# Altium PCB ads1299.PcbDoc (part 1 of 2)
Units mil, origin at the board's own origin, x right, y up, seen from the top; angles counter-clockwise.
Board outline 3937.01 x 3937.01 mil, 4 copper layers (Top Layer, internal_Layer 1, Internal_Layer 2, Bottom Layer), stack 23.756 mil thick; 175 components, 124 nets, 575 pads, 101 vias.
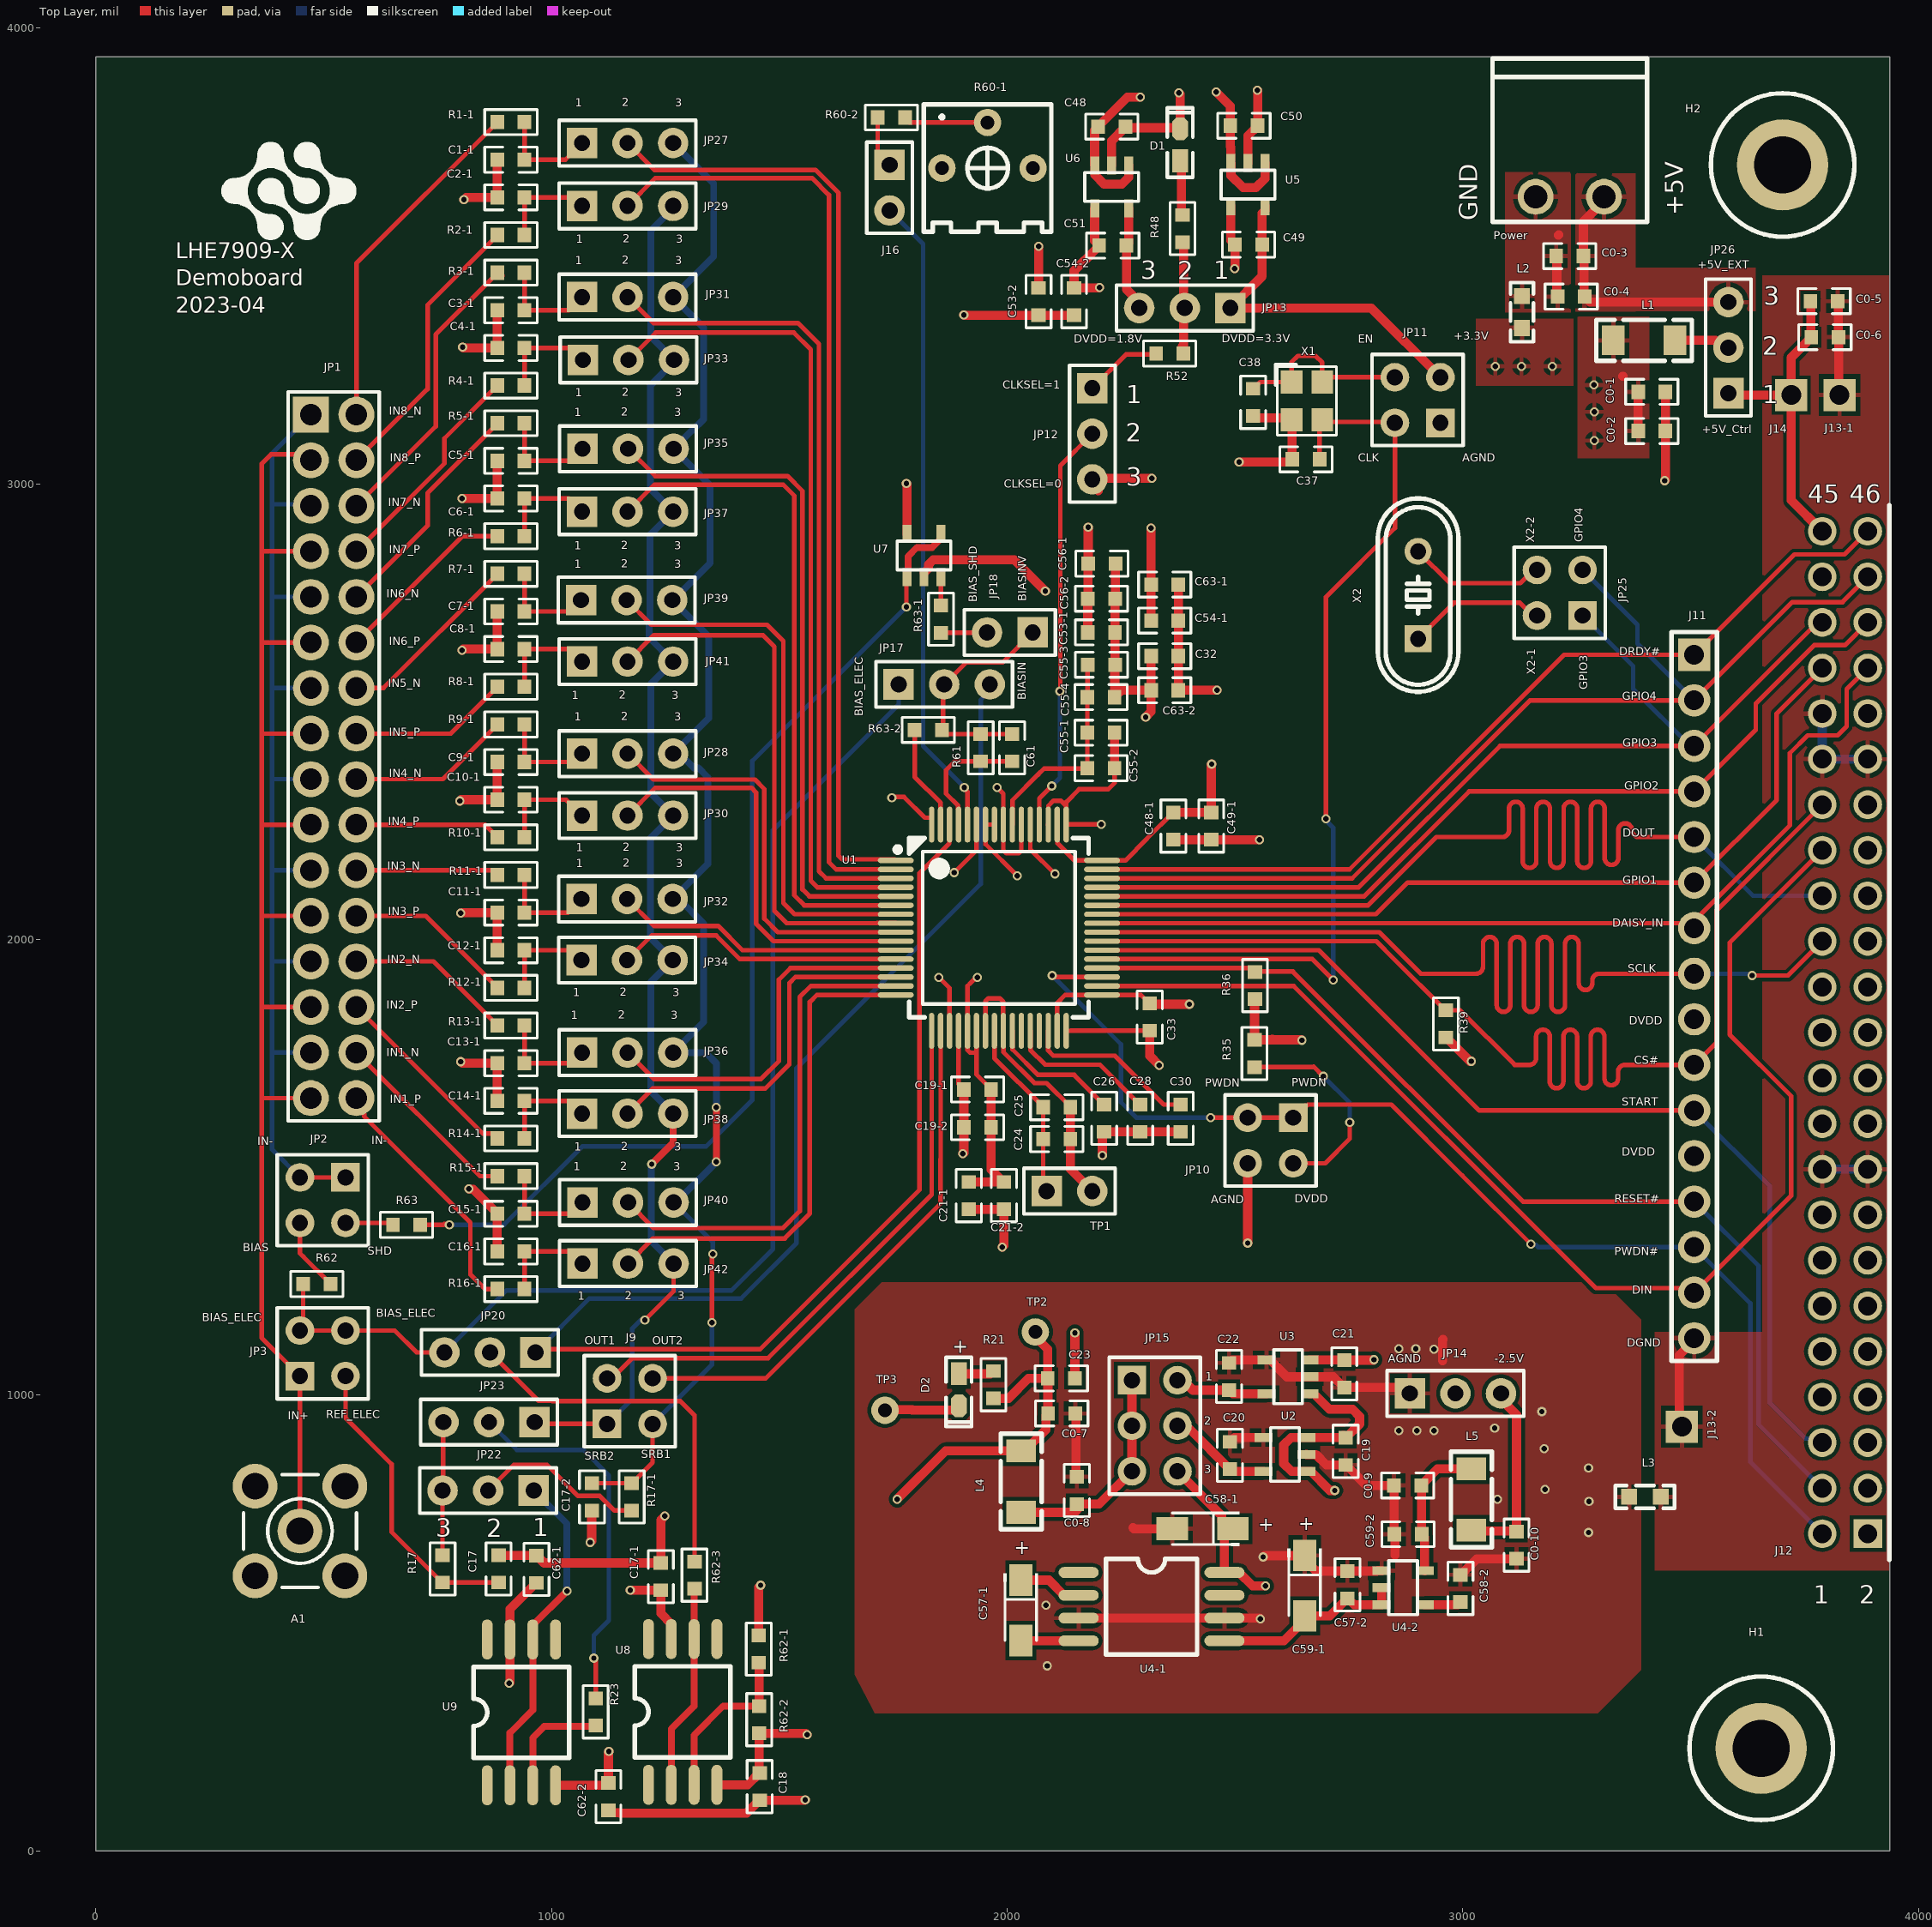
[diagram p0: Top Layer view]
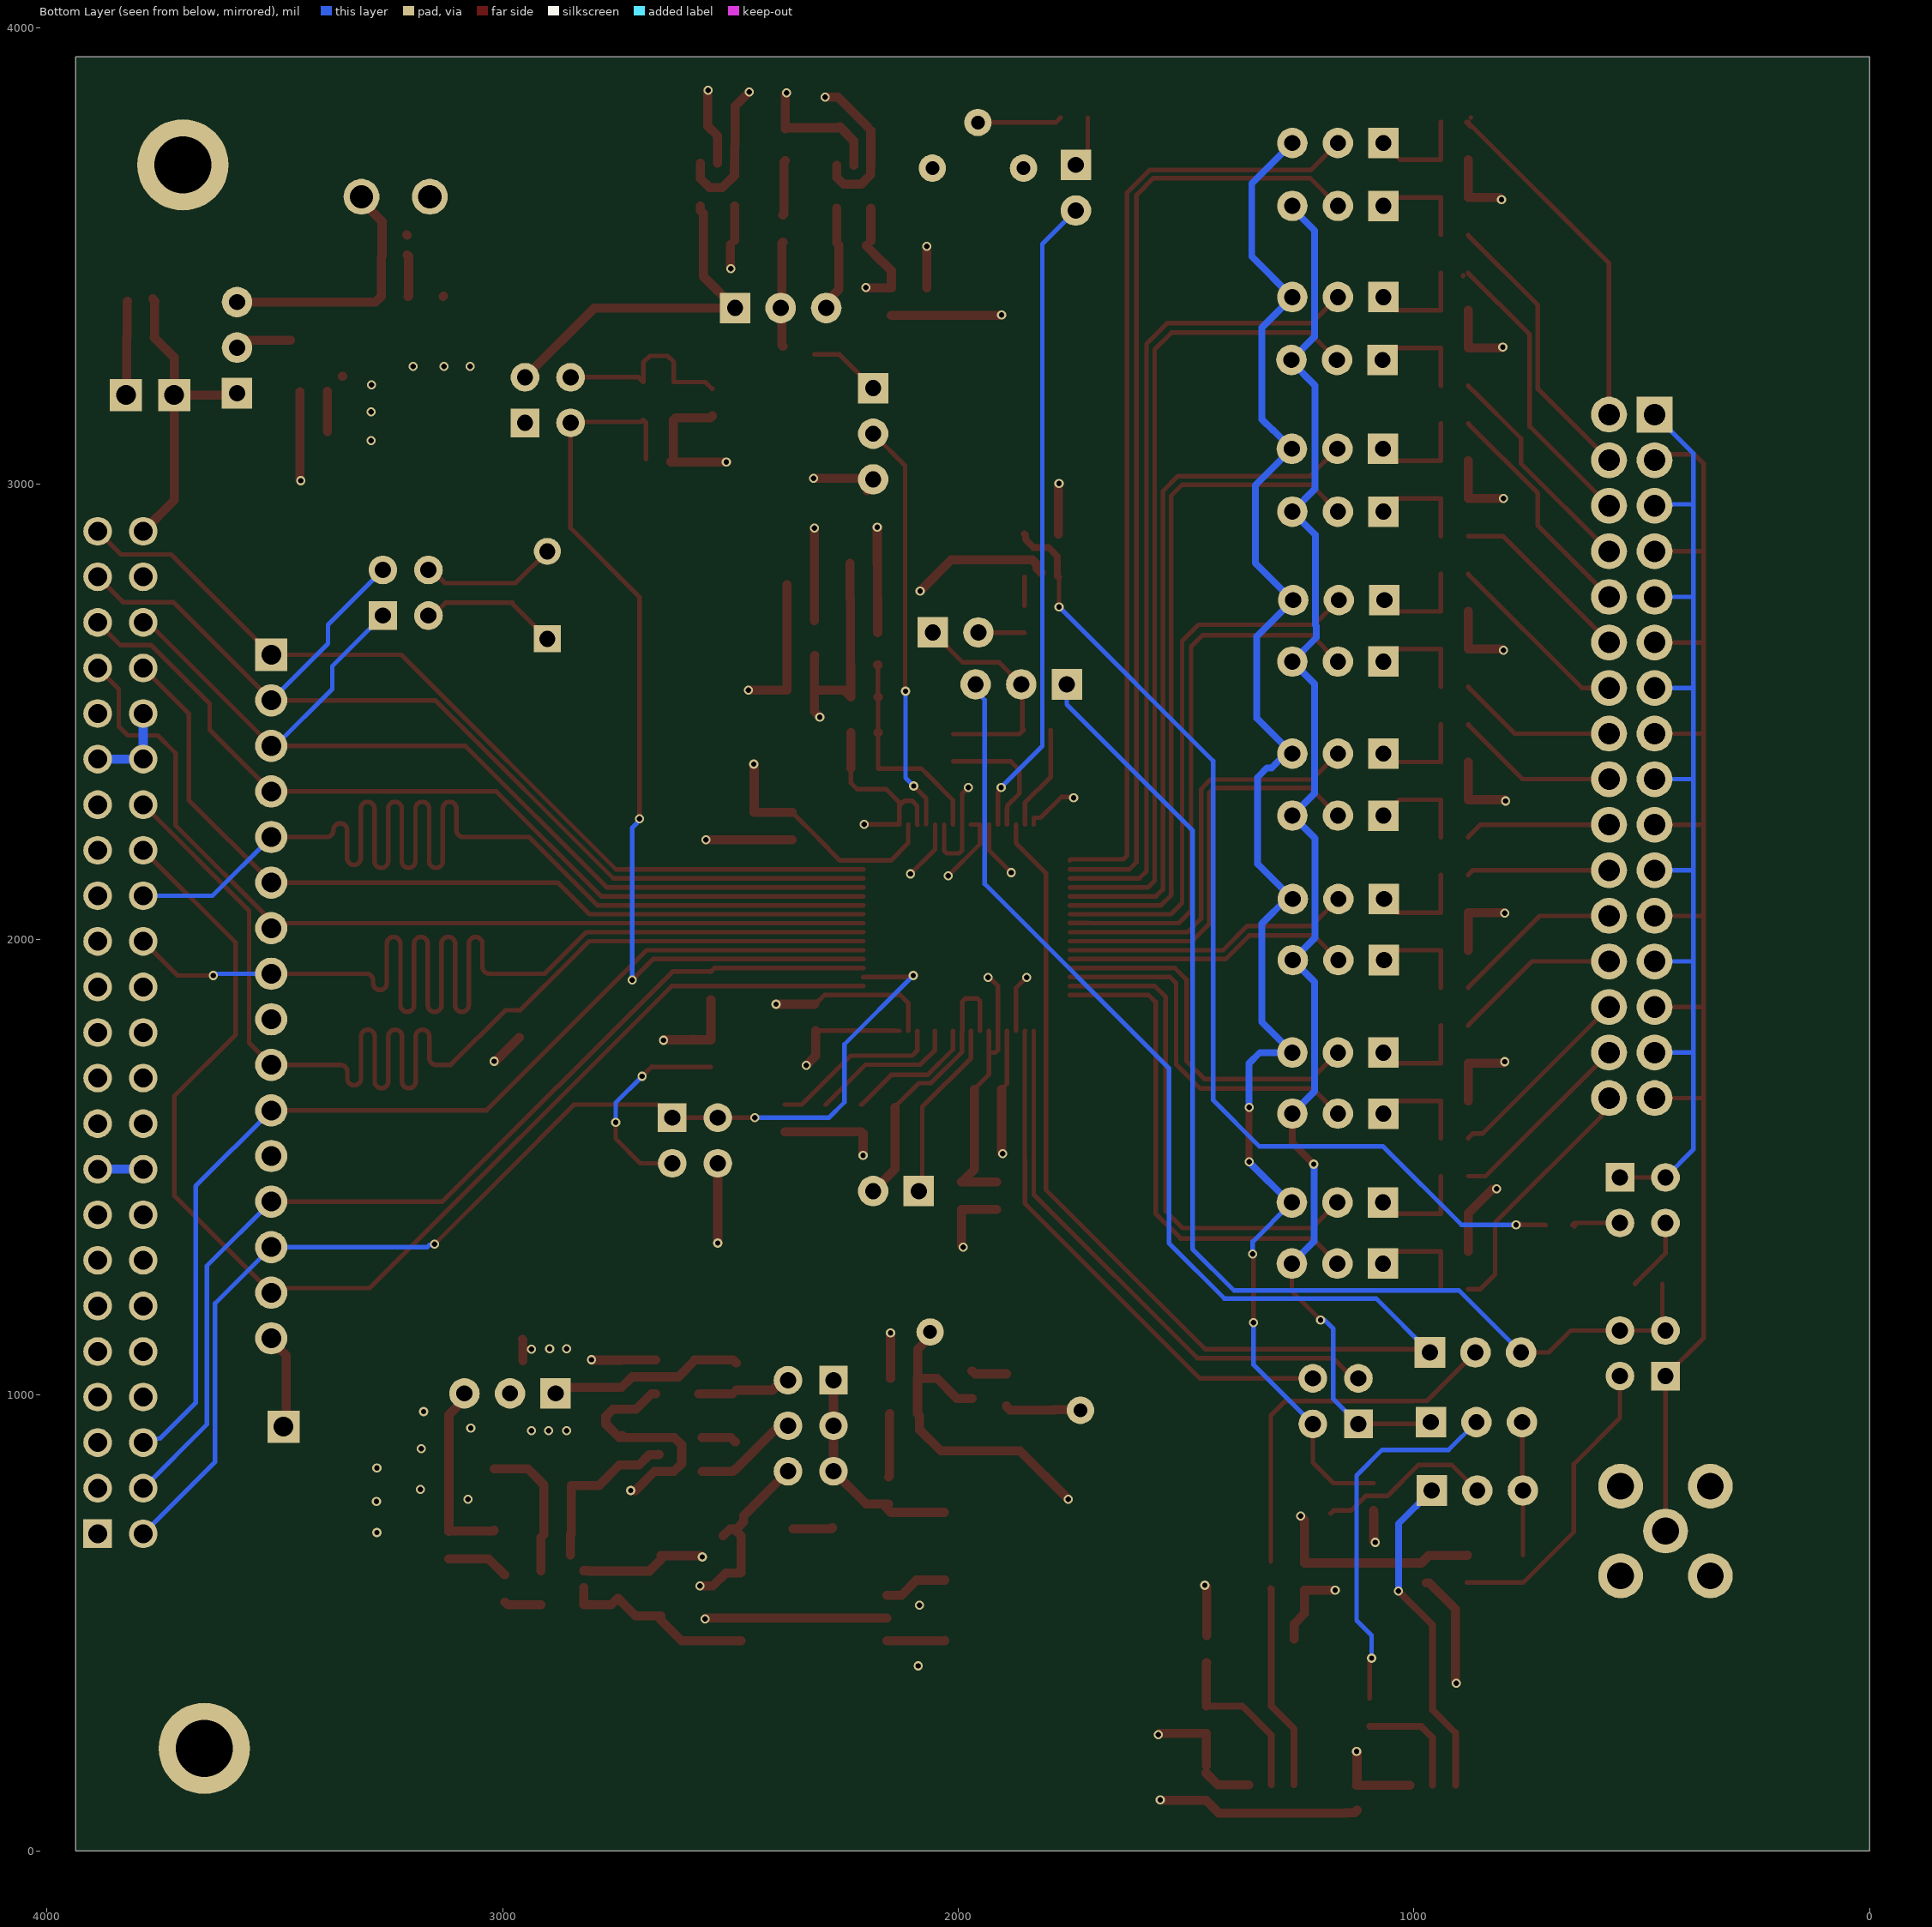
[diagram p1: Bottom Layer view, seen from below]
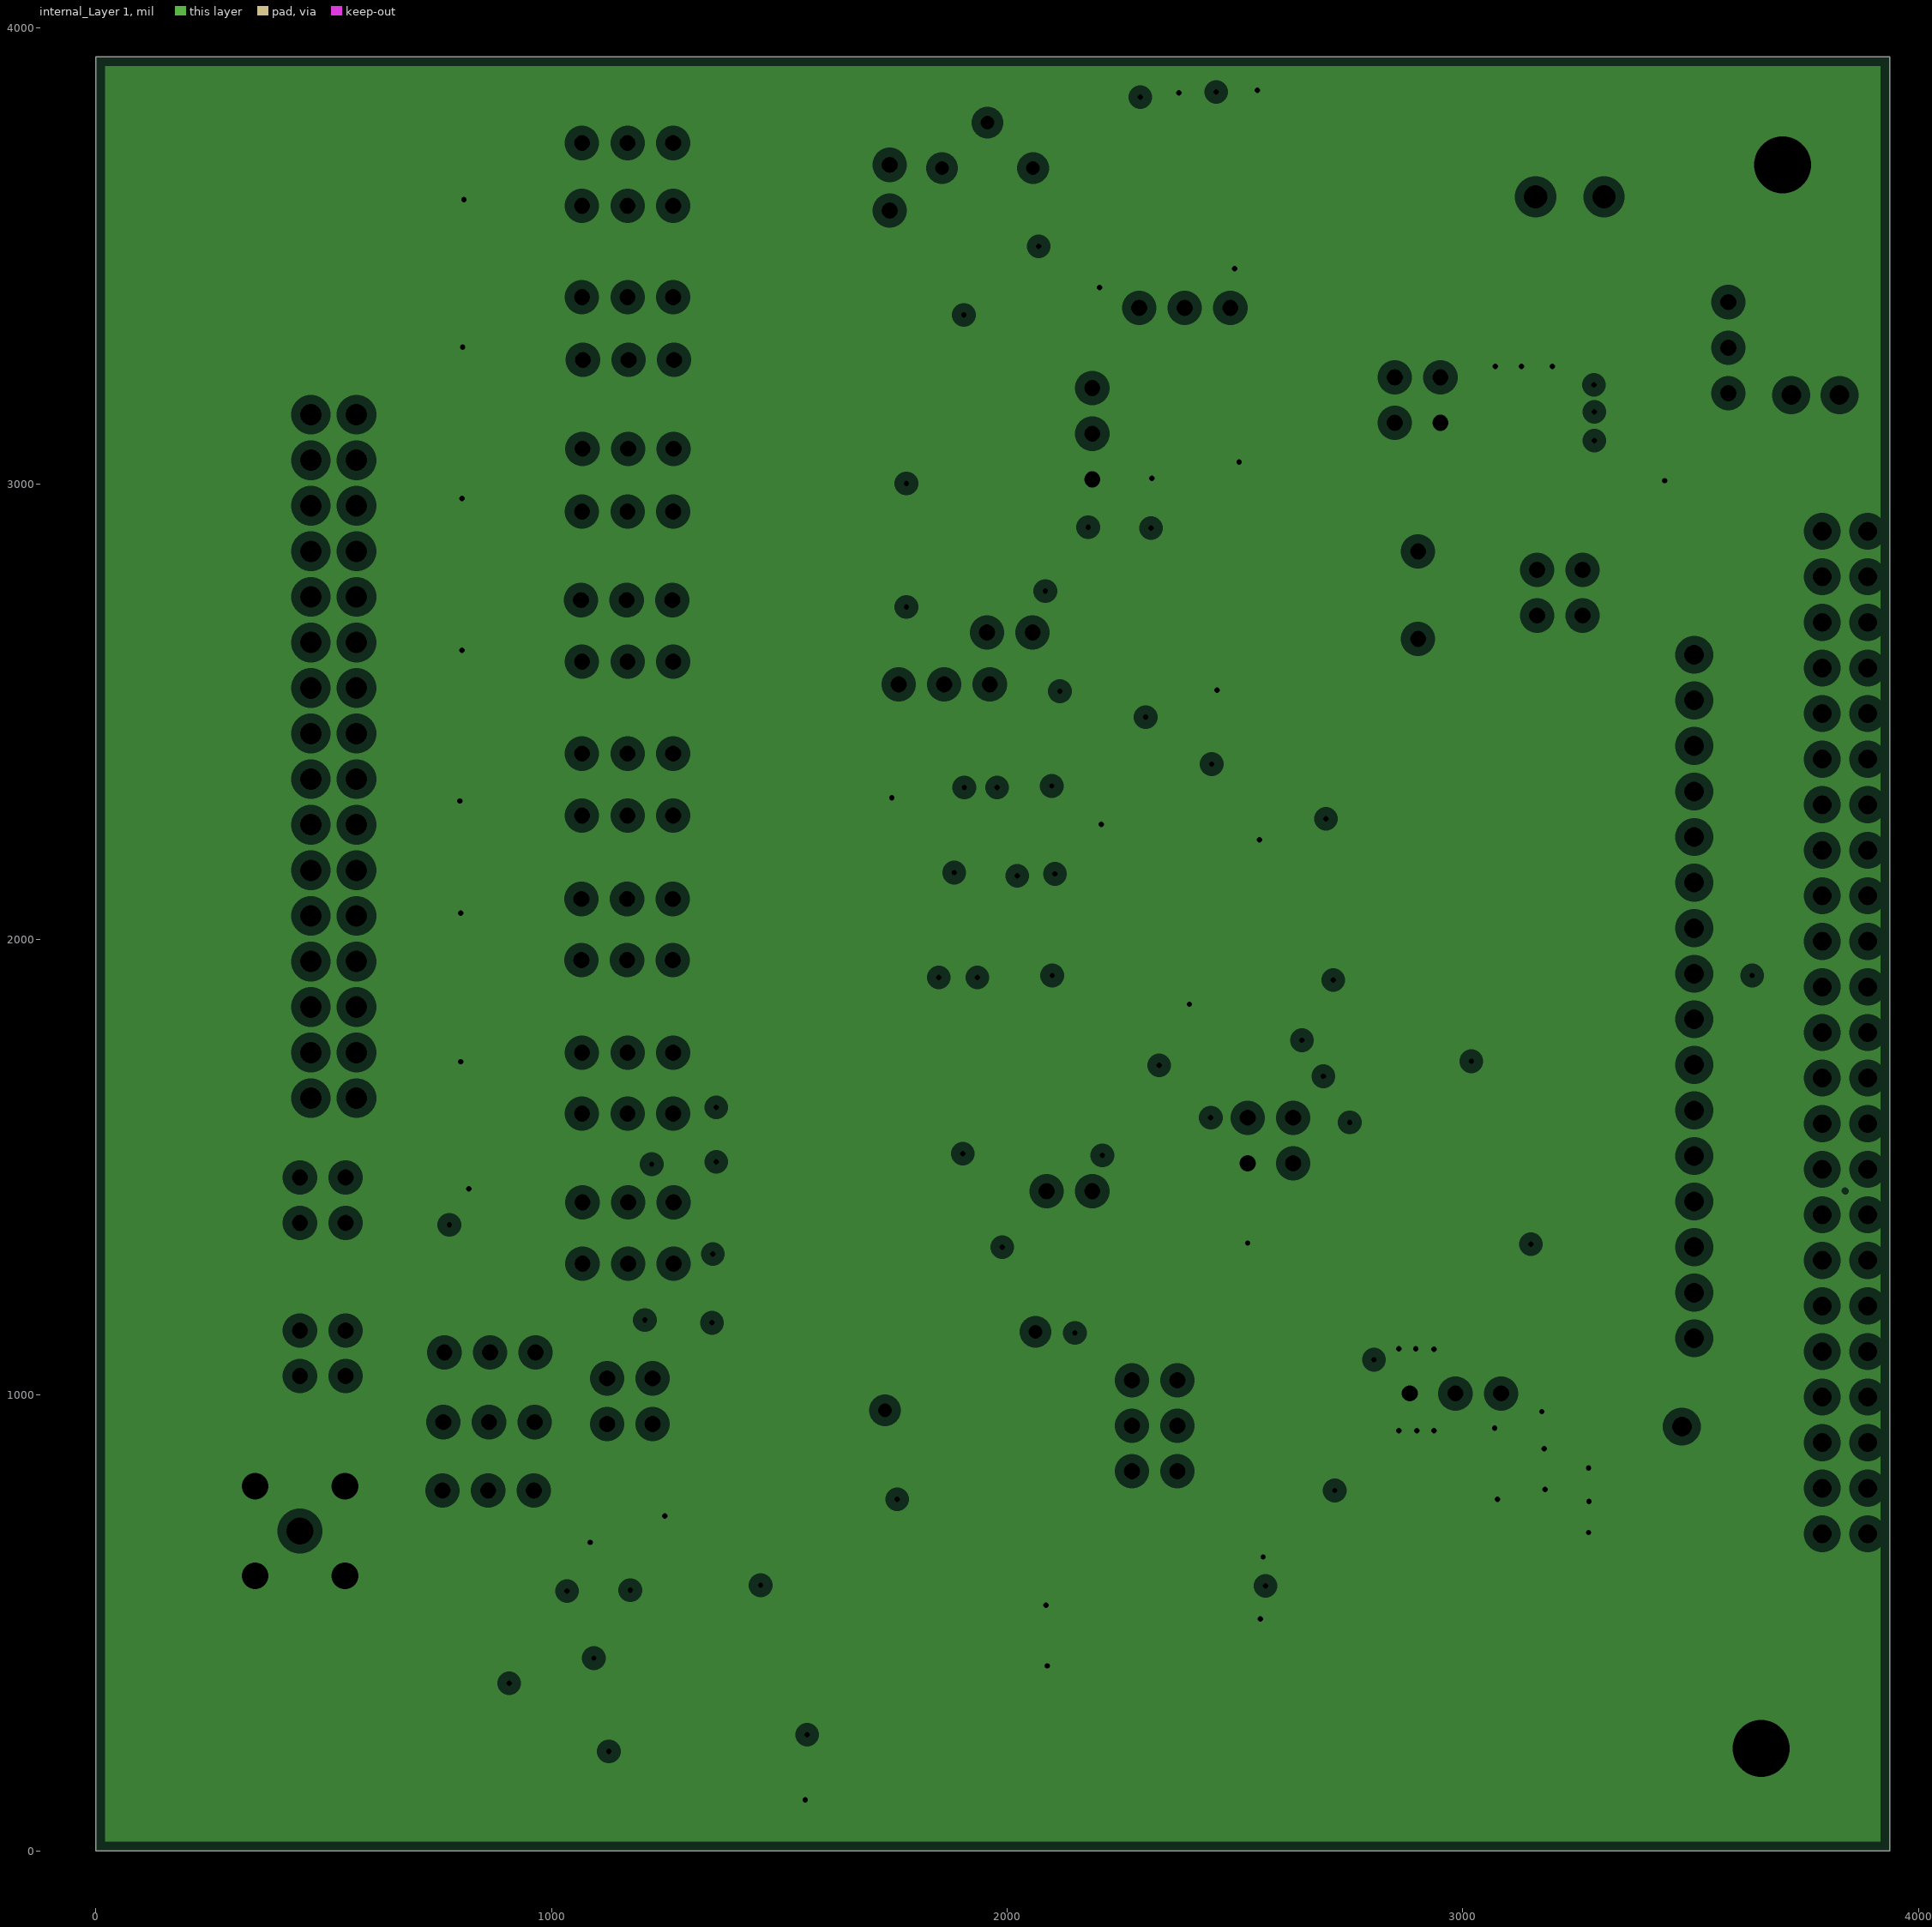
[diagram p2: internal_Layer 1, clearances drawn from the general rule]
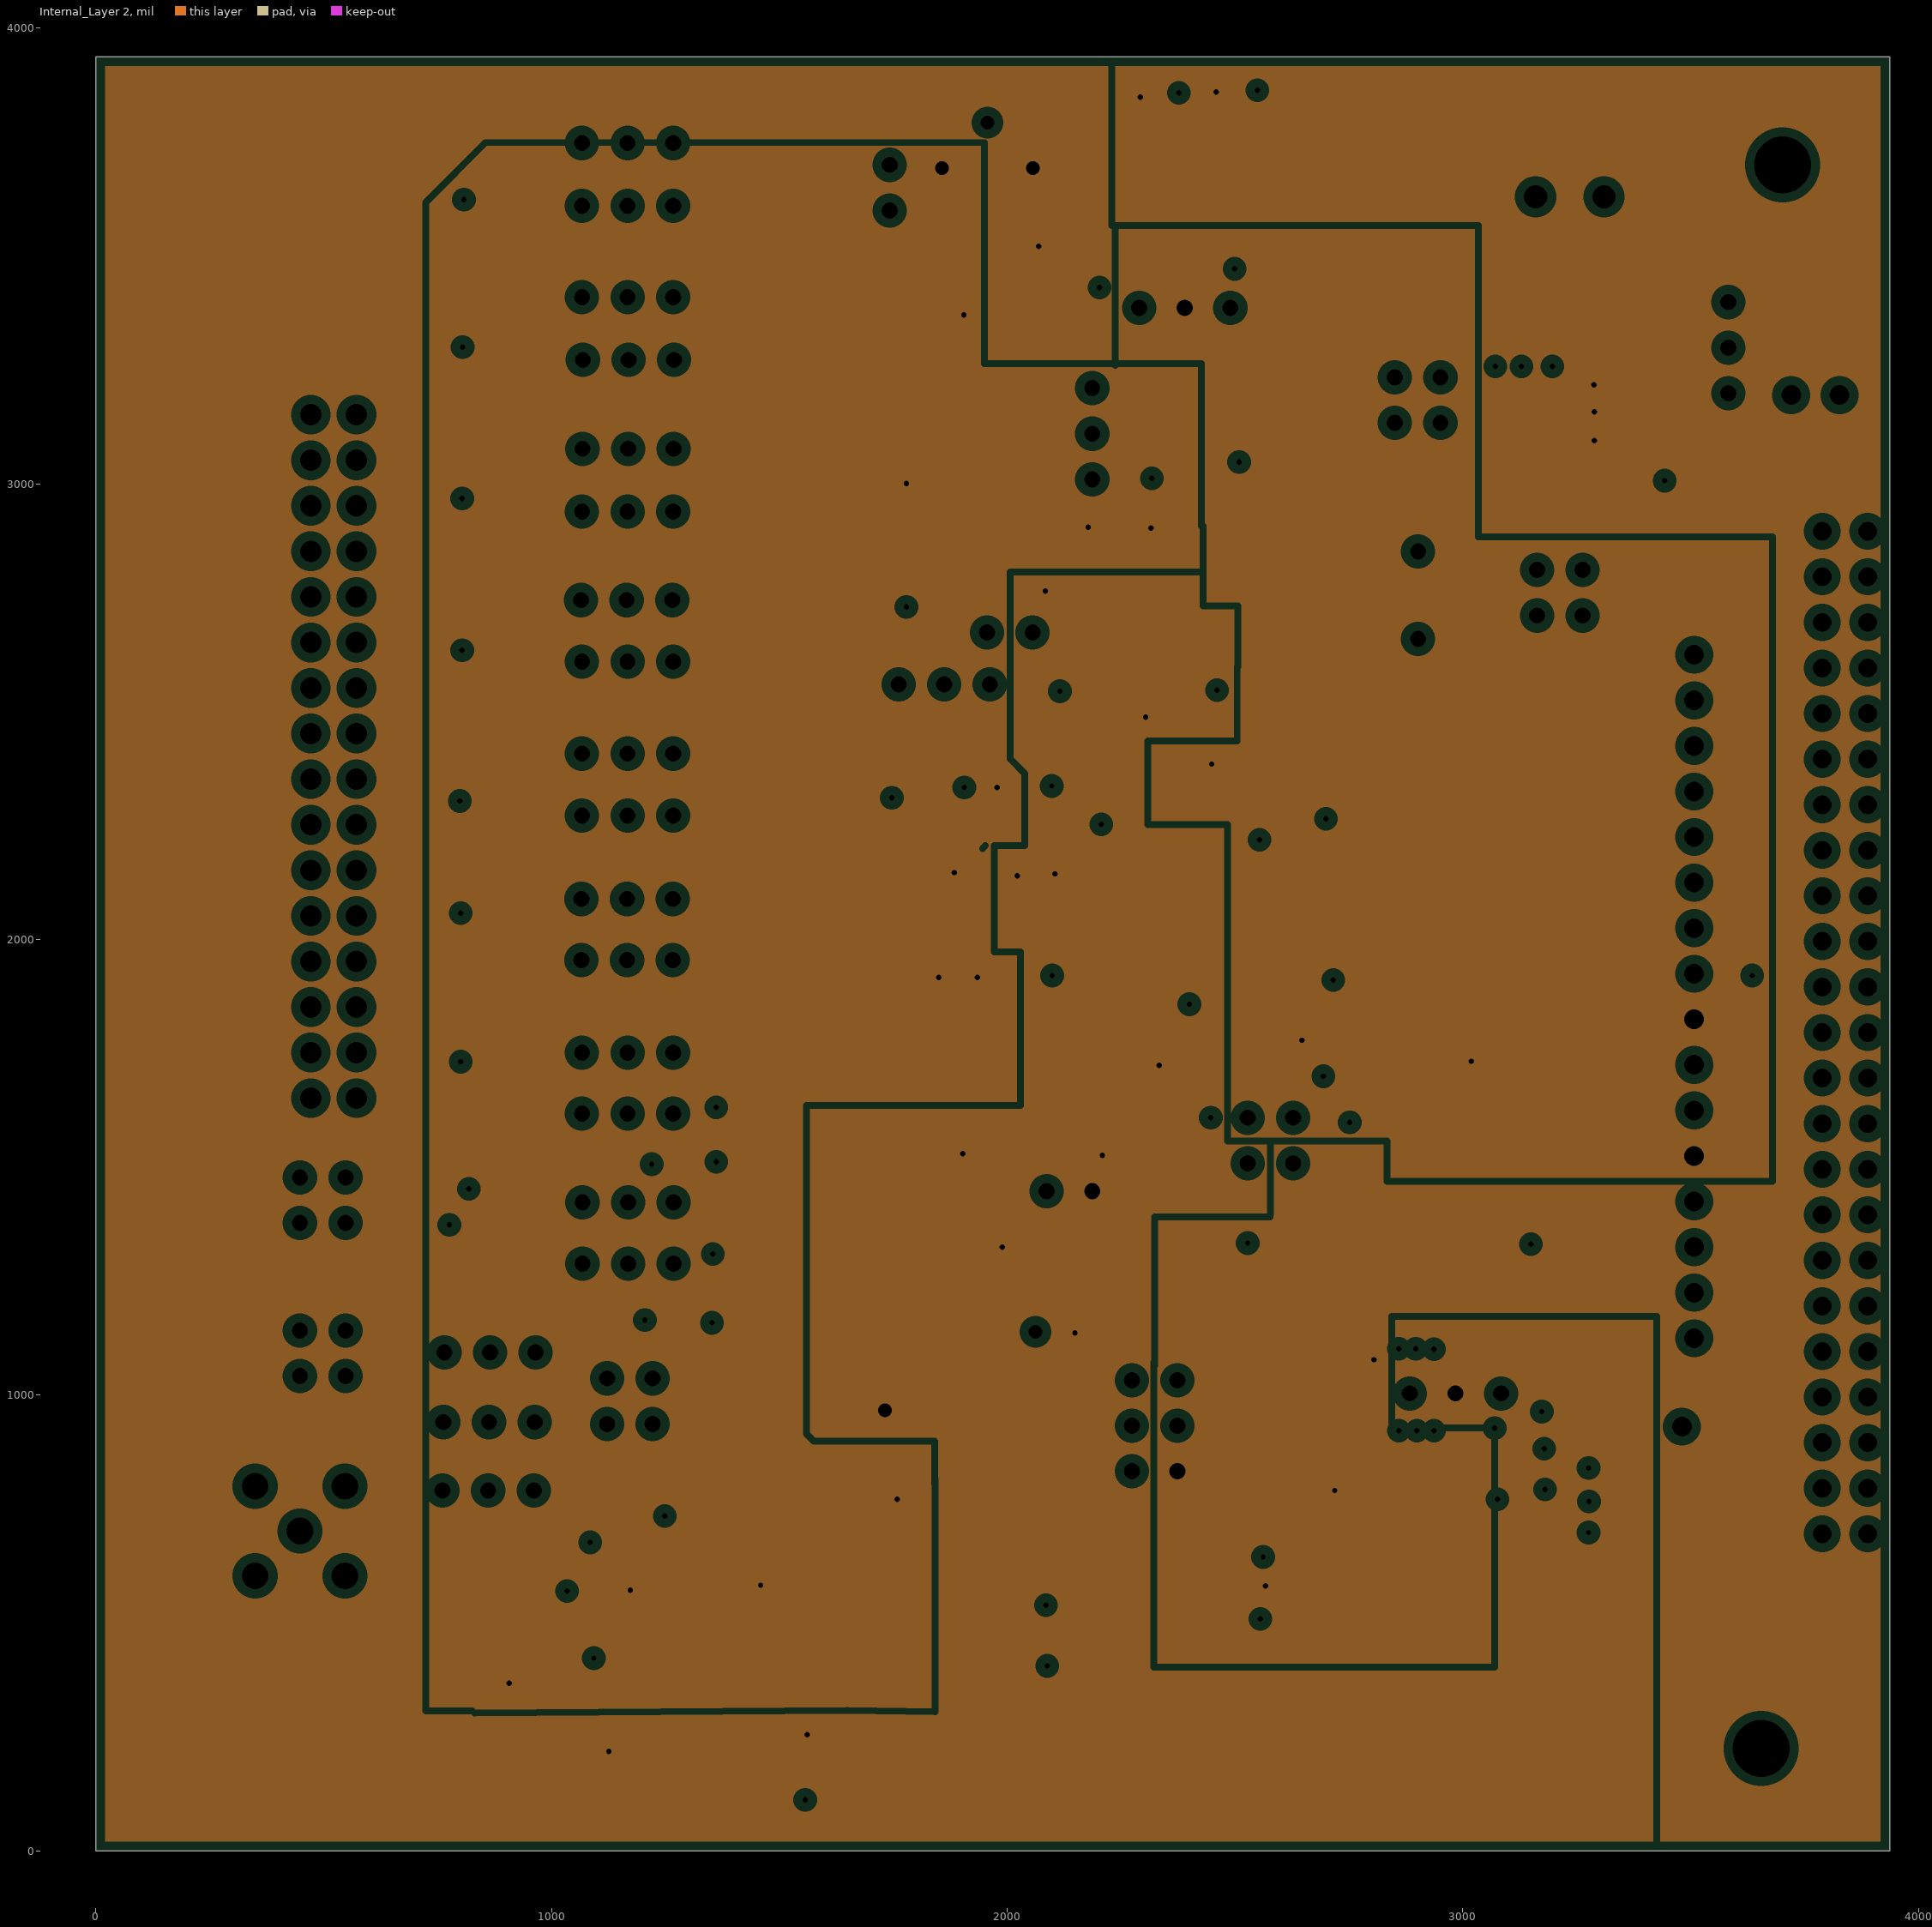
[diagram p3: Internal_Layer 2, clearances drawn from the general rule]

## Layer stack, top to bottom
Top Solder: solder mask 0.4, Solder Resist, Dk 3.5
Top Layer: signal copper 1.4
Dielectric 2: prepreg 2.8, PP-006, Dk 4.1
internal_Layer 1: plane copper 1.378, net AGND
Dielectric 1: dielectric 12.6, FR-4, Dk 4.8
Internal_Layer 2: plane copper 1.378, net (Multiple Nets)
Dielectric 3: prepreg 2.8, PP-006, Dk 4.1
Bottom Layer: signal copper 1.4
Bottom Solder: solder mask 0.4, Solder Resist, Dk 3.5

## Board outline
0,0 3937.01,0 3937.01,3937.01 0,3937.01

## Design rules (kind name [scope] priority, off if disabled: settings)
Clearance [All] p1: gap=8 ignorepadtopadclearanceinfootprint=TRUE except(0: Arc-Hole Track-Hole SMDPad-Hole THPad-Hole Via-Hole Fill-Hole Poly-Hole Region-Hole Text-Hole)
DiffPairsRouting [All] p1: maxlimit=10 minlimit=8 mostfreqgap=8 toplayer_minwidth=10 toplayer_maxwidth=15 toplayer_prefwidth=10 bottomlayer_minwidth=10 bottomlayer_maxwidth=15 bottomlayer_prefwidth=10 maxuncoupledlength=500
Height [All] p1: minheight=0 maxheight=5000 prefheight=500
HoleSize [All] p1: absolutevalues=TRUE maxlimit=200 minlimit=0 maxpercent=80.000 minpercent=20.000
HoleToHoleClearance [All] p1: gap=0 allowstackedmicrovias=TRUE
MatchedLengths [InNetClass('data')] p1: tolerance=10 checknetsindiffpair=FALSE checkdiffpairvsdiffpair=TRUE checkxsignals=TRUE checkothers=TRUE
MinimumSolderMaskSliver [All] p1: minsoldermaskwidth=0
PlaneClearance [All] p1: clearance=20
PlaneConnect [All] p1: planeconnectstyle=Relief reliefexpansion=20 reliefentries=4 reliefconductorwidth=10 reliefairgap=10
PolygonConnect [All] p1: thpad.connectstyle=Relief thpad.reliefconductorwidth=10 thpad.reliefentries=4 thpad.polygonreliefangle="90 Angle" thpad.airgapwidth=10 smdpad.connectstyle=Relief smdpad.reliefconductorwidth=10 smdpad.reliefentries=4 smdpad.polygonreliefangle="90 Angle" smdpad.airgapwidth=10 via.connectstyle=Direct via.reliefconductorwidth=10 via.reliefentries=4 via.polygonreliefangle="90 Angle" via.airgapwidth=10
RoutingVias [All] p1: holewidth=12 width=20 viastyle="Through Hole" minholewidth=12 minwidth=20 maxholewidth=12 maxwidth=20
SilkToSilkClearance [All] p1: silktosilkclearance=0
SilkToSolderMaskClearance [IsPad] p1: minsilkscreentomaskgap=0 clearancetoexposedcopper=TRUE
SolderMaskExpansion [All] p1: expansion=4
Width [InNetClass('All Nets')] p1: maxlimit=20 minlimit=10 preferedwidth=10 minimp=50.000000 maximp=50.000000 favimp=50.000000
21 further rules are at their usual default settings.

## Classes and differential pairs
component class ads1299_Regulators: C0-7 C0-8 C0-9 C0-10 C19 C20 C21 C22 C23 C48 C49 C50 C51 C57-1 C57-2 C58-1 C58-2 C59-1 C59-2 D1 D2 JP13 JP14 JP15 L4 L5 R21 R48 U2 U3 U4-1 U4-2 U5 U6
component class ads1299_main: C17-1 C17-2 C18 C19-1 C19-2 C21-1 C21-2 C24 C25 C26 C28 C30 C32 C33 C37 C38 C48-1 C49-1 C53-1 C53-2 C54-1 C54-2 C55-1 C55-2 C55-3 C55-4 C56-1 C56-2 C61 C62-1 C62-2 C63-1 C63-2 J9 J16 JP10 JP11 JP12 JP17 JP18 JP20 JP22 JP23 R17-1 R23 R35 R36 R39 R52 R60-1 R60-2 R61 R62-1 R62-2 R62-3 R63-1 R63-2 TP1 TP2 TP3 U1 U7 U8 U9 X1
component class ads1299_Interface: C0-1 C0-2 C0-3 C0-4 C0-5 C0-6 J11 J12 J13-1 J13-2 J14 JP25 JP26 L1 L2 L3 Power X2
component class ads1299_Ain: A1 C1-1 C2-1 C3-1 C4-1 C5-1 C6-1 C7-1 C8-1 C9-1 C10-1 C11-1 C12-1 C13-1 C14-1 C15-1 C16-1 C17 H1 H2 JP1 JP2 JP3 JP27 JP28 JP29 JP30 JP31 JP32 JP33 JP34 JP35 JP36 JP37 JP38 JP39 JP40 JP41 JP42 R1-1 R2-1 R3-1 R4-1 R5-1 R6-1 R7-1 R8-1 R9-1 R10-1 R11-1 R12-1 R13-1 R14-1 R15-1 R16-1 R17 R62 R63
differential pair IN8: +IN8_P -IN8_N
differential pair IN7: +IN7_P -IN7_N
differential pair IN6: +IN6_P -IN6_N
differential pair IN5: +IN5_P -IN5_N
differential pair IN4: +IN4_P -IN4_N
differential pair IN3: +IN3_P -IN3_N
differential pair IN2: +IN2_P -IN2_N
differential pair IN1: +IN1_P -IN1_N

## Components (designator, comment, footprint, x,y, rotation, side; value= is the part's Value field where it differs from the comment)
A1 "SMA/SMB" SMB_V-RJ45 448,702 r0 top
C0-1 "10uF" 0603C 3414.92,3202 r180 top
C0-2 "0.1uF" 0603C 3415,3116 r180 top
C0-3 "10uF" 0603C 3235,3500 r0 top
C0-4 "0.1uF" 0603C 3238,3411 r0 top
C0-5 "10uF" 0603C 3793.08,3401 r180 top
C0-6 "0.1uF" 0603C 3795,3322 r180 top
C0-7 "10uF" 0603C 2120,960 r180 top
C0-8 "10uF" 0603C 2153,790.92 r270 top
C0-9 "10uF" 0603C 2879.08,802 r0 top
C0-10 "10uF" 0603C 3118,671 r90 top
C1-1 "4.7nF" 0603C 911,3711.39 r0 top
C2-1 "4.7nF" 0603C 911,3628.77 r180 top
C3-1 "4.7nF" 0603C 911,3380.94 r0 top
C4-1 "4.7nF" 0603C 911,3298.32 r180 top
C5-1 "4.7nF" 0603C 911,3050.48 r0 top
C6-1 "4.7nF" 0603C 911,2967.87 r180 top
C7-1 "4.7nF" 0603C 911,2720.03 r0 top
C8-1 "4.7nF" 0603C 911,2637.42 r180 top
C9-1 "4.7nF" 0603C 911,2389.58 r0 top
C10-1 "4.7nF" 0603C 911,2306.97 r180 top
C11-1 "4.7nF" 0603C 911,2059.13 r0 top
C12-1 "4.7nF" 0603C 911,1976.52 r180 top
C13-1 "4.7nF" 0603C 911,1728.68 r0 top
C14-1 "4.7nF" 0603C 911,1646.06 r180 top
C15-1 "4.7nF" 0603C 911,1398.23 r0 top
C16-1 "4.7nF" 0603C 911,1315.61 r180 top
C17 "4.7nF" 0603C 884,619 r270 top
C17-1 "1uF" 0603C 1240,602 r270 top
C17-2 "NI" 0603C 1089,777 r90 top
C18 "1uF" 0603C 1457,141 r270 top
C19 "1uF" 0603C 2743,876.92 r90 top
C19-1 "1uF" 0603C 1935,1671 r0 top
C19-2 "0.1uF" 0603C 1935,1588 r0 top
C20 "1uF" 0603C 2489,867.92 r270 top
C21 "1uF" 0603C 2740,1047 r90 top
C21-1 "0.1uF" 0603C 1916,1438 r90 top
C21-2 "1uF" 0603C 1993,1438 r90 top
C22 "1uF" 0603C 2487,1041 r270 top
C23 "0.1uF" 0603C 2119,1037 r180 top
C24 "10uF" 0603C 2109,1562 r0 top
C25 "0.1uF" 0603C 2109,1632 r180 top
C26 "1uF" 0603C 2213,1608 r90 top
C28 "22uF/100uF" 0603C 2292,1608 r90 top
C30 "1uF" 0603C 2381,1608 r90 top
C32 "1uF" 0603C 2346,2622 r180 top
C33 "1uF" 0603C 2313,1830.08 r270 top
C37 "15pF" 0603C 2656,3054 r0 top
C38 "0.01uF" 0603C 2540,3178.92 r270 top
C48 "1uF" 0603C 2229.92,3784 r180 top
C48-1 "0.1uF" 0603C 2365,2249 r90 top
C49 "1uF" 0603C 2530,3525 r0 top
C49-1 "1uF" 0603C 2448,2249 r90 top
C50 "1uF" 0603C 2519.92,3786 r180 top
C51 "1uF" 0603C 2232,3523 r0 top
C53-1 "0.1uF" 0603C 2206.92,2674 r180 top
C53-2 "1uF" 0603C 2069,3400 r270 top
C54-1 "0.1uF" 0603C 2346,2700 r180 top
C54-2 "1uF" 0603C 2147,3400 r270 top
C55-1 "0.1uF" 0603C 2206,2454 r180 top
C55-2 "1uF" 0603C 2206,2376 r180 top
C55-3 "NI" 0603C 2207,2603 r0 top
C55-4 "NI" 0603C 2206,2532 r0 top
C56-1 "0.1uF" 0603C 2208,2825 r180 top
C56-2 "1uF" 0603C 2207,2748 r180 top
C57-1 "10uF" Tantalum_cap 2030,528 r270 top value=1uF
C57-2 "1uF" 0603C 2747,584 r270 top
C58-1 "0.1uF" Tantalum_cap 2429,707 r180 top value=1uF
C58-2 "1uF" 0603C 2995,576 r270 top
C59-1 "10uF" Tantalum_cap 2653,582 r270 top value=1uF
C59-2 "1uF" 0603C 2880,695 r0 top
C61 "0.01uF" 0603C 2011,2421 r270 top
C62-1 "1uF" 0603C 967,618 r270 top
C62-2 "1uF" 0603C 1125,119 r270 top
C63-1 "0.1uF" 0603C 2346,2779 r180 top
C63-2 "0.1uF" 0603C 2346,2547 r0 top
D1 "绿灯 0603" "LED 0603G" 2380,3744 r90 top
D2 "绿灯 0603" "LED 0603G" 1894,1012 r270 top
H1 "M3" M3x4_L 3655,225 r0 top
H2 "M3" M3x4_L 3702,3700 r0 top
J9 "Header 2X2" HDR2.54-LI-2x2P 1172,987 r0 top
J11 "KH-2.54PH180-1X16P-L11.5" HDR-TH_16P-P2.54 3508,1875 r270 top
J12 "X6521WR-2x23H-C30D60" HDR-TH_2x23P-P2.54-Bent 3839,1796 r90 top
J13-1 "Header_1P" HDR-TH_1P 3827,3195 r0 top
J13-2 "Header_1P" HDR-TH_1P 3481,931 r0 top
J14 "Header_1P" HDR-TH_1P 3721,3195 r0 top
J16 "Header_2P_2.54" HDR2.54-LI-2P 1742,3650 r270 top
JP1 "B-2100S32P-B110" HDR-TH_32P-P2.54-V-M-R2-C16-S2.54 522,2402 r270 top
JP2 "Header 2X2" HDR2.54-LI-2x2P 498,1428 r180 top
JP3 "Header 2X2" HDR2.54-LI-2x2P 498,1092 r0 top
JP10 "Header 2X2" HDR2.54-LI-2x2P 2578,1559 r180 top
JP11 "Header 2X2_2.54" HDR2.54-LI-2x2P 2901,3184 r90 top
JP12 "HDR-1X3" HDR2.54-LI-3P 2187,3110 r270 top
JP13 "HDR-1X3" HDR2.54-LI-3P 2390,3386 r180 top
JP14 "HDR-1X3" HDR2.54-LI-3P 2984,1004 r0 top
JP15 "Header 3X2" HDR2.54-LI-2x3P 2324,933 r270 top
JP17 "HDR-1X3" HDR2.54-LI-3P 1862,2560 r0 top
JP18 "Header_2P_2.54" HDR2.54-LI-2P 2006,2674 r180 top
JP20 "HDR-1X3" HDR2.54-LI-3P 865,1094 r180 top
JP22 "HDR-1X3" HDR2.54-LI-3P 861,791 r180 top
JP23 "HDR-1X3" HDR2.54-LI-3P 863,941 r180 top
JP25 "Header 2X2" HDR2.54-LI-2x2P 3213,2761 r90 top
JP26 "HDR-1X3" HDR2.54-LI-3P 3583,3299 r90 top
JP27 "HDR-1X3" HDR2.54-LI-3P 1167,3748 r0 top
JP28 "HDR-1X3" HDR2.54-LI-3P 1167,2408 r0 top
JP29 "HDR-1X3" HDR2.54-LI-3P 1167,3610 r0 top
JP30 "HDR-1X3" HDR2.54-LI-3P 1167,2272 r0 top
JP31 "HDR-1X3" HDR2.54-LI-3P 1167,3410 r0 top
JP32 "HDR-1X3" HDR2.54-LI-3P 1166,2089 r0 top
JP33 "HDR-1X3" HDR2.54-LI-3P 1169,3272 r0 top
JP34 "HDR-1X3" HDR2.54-LI-3P 1166,1955 r0 top
JP35 "HDR-1X3" HDR2.54-LI-3P 1168,3077 r0 top
JP36 "HDR-1X3" HDR2.54-LI-3P 1167,1752 r0 top
JP37 "HDR-1X3" HDR2.54-LI-3P 1167,2939 r0 top
JP38 "HDR-1X3" HDR2.54-LI-3P 1167,1618 r0 top
JP39 "HDR-1X3" HDR2.54-LI-3P 1165,2745 r0 top
JP40 "HDR-1X3" HDR2.54-LI-3P 1168,1423 r0 top
JP41 "HDR-1X3" HDR2.54-LI-3P 1167,2610 r0 top
JP42 "HDR-1X3" HDR2.54-LI-3P 1168,1289 r0 top
L1 "3.3uH" "L 1206" 3398,3315 r180 top
L2 "0Ω@100MHz" "L 0603" 3130,3377 r270 top
L3 "0Ω@100MHz" "L 0603" 3400,777 r0 top
L4 "3.3uH" "L 1206" 2031,810.5 r270 top
L5 "3.3uH" "L 1206" 3019,771 r270 top
Power "CONN-TH-F3.81-2P" CONN-TH_XY2500R-F-3.81-2P 3235,3630 r180 top
R1-1 "4.99kΩ" 0603R 911,3794 r0 top
R2-1 "4.99kΩ" 0603R 911,3546.16 r0 top
R3-1 "4.99kΩ" 0603R 911,3463.55 r0 top
R4-1 "4.99kΩ" 0603R 911,3215.71 r0 top
R5-1 "4.99kΩ" 0603R 911,3133.1 r0 top
R6-1 "4.99kΩ" 0603R 911,2885.26 r0 top
R7-1 "4.99kΩ" 0603R 911,2802.65 r0 top
R8-1 "4.99kΩ" 0603R 911,2554.81 r0 top
R9-1 "4.99kΩ" 0603R 911,2472.19 r0 top
R10-1 "4.99kΩ" 0603R 911,2224.35 r0 top
R11-1 "4.99kΩ" 0603R 911,2141.74 r0 top
R12-1 "4.99kΩ" 0603R 911,1893.9 r0 top
R13-1 "4.99kΩ" 0603R 911,1811.29 r0 top
R14-1 "4.99kΩ" 0603R 911,1563.45 r0 top
R15-1 "4.99kΩ" 0603R 911,1480.84 r0 top
R16-1 "4.99kΩ" 0603R 911,1233 r0 top
R17 "4.99kΩ" 0603R 761,619 r270 top
R17-1 "0Ω" 0603R 1176,777 r90 top
R21 "100Ω" 0603R 1970,1023 r270 top
R23 "0Ω" 0603R 1097,305 r270 top
R35 "10KΩ" 0603R 2543,1750 r270 top
R36 "10KΩ" 0603R 2544,1899 r270 top
R39 "10KΩ" 0603R 2963,1815 r90 top
R48 "100Ω" 0603R 2385,3560.08 r270 top
R52 "10KΩ" 0603R 2357,3286 r0 top
R60-1 "可变电阻10kΩ" RES-ADJ-TH_3362P 1957,3743 r0 top value=10kΩ
R60-2 "0Ω" 0603R 1746,3804 r180 top
R61 "392KΩ" 0603R 1942,2421 r90 top
R62 "4.99kΩ" 0603R 485,1244 r180 top
R62-1 "2MΩ" 0603R 1455,443 r90 top
R62-2 "2MΩ" 0603R 1456,288 r90 top
R62-3 "0Ω" 0603R 1314,605.08 r90 top
R63 "4.99kΩ" 0603R 682,1374 r0 top
R63-1 "0Ω/5kΩ" 0603R 1855,2703 r270 top
R63-2 "0Ω" 0603R 1827,2460 r0 top
TP1 "Header_2P_2.54" HDR2.54-LI-2P 2137,1448 r0 top
TP2 "测试点" TestPoint_Pad 2062,1139 r90 top
TP3 "测试点" TestPoint_Pad 1732,967 r180 top
U1 "ADS129x" LQFP-64 1982,2026 r270 top
U2 "LP5907MFX-3.0/NOPB" SOT23-5 2657,832.6 r90 top
U3 "LP5907MFX-2.5/NOPB" SOT23-5 2664,1003 r90 top
U4-1 "ICL7660M/TR" SOIC-8 2157,611 r0 top
U4-2 "TPS72325DBVR" SOT23-5 2822,615 r270 top
U5 "LP5907MFX-3.3/NOPB" SOT23-5 2566,3704 r180 top
U6 "LP5907MFX-1.8/NOPB" SOT23-5 2267,3699 r180 top
U7 "TLV9061IDBVR" SOT23-5 1780.2,2795.51 r0 top
U8 "OPA376AID" SOIC-8 1213,145 r90 top
U9 "OPA376AID" SOIC-8 859,144 r90 top
X1 "SX3M2.048M20F30TNN" "OSC 3225-4P" 2658,3182 r270 top value=2.048MHz
X2 "X49SD4096MSD2SC" HC-49US 2902,2756 r90 top value=4.096MHz

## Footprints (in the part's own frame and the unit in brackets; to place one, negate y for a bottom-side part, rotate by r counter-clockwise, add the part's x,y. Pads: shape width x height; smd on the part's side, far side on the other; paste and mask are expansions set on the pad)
0603C [mm]
  rect 0.76x0.8 smd: 1(-0.76,0) 2(0.76,0)
  silkscreen extent -1.46,-0.7 1.46,0.7, body extent -0.8,-0.4 0.8,0.4, height 0.3
0603R [mm]
  rect 0.76x0.8 smd: 1(-0.76,0) 2(0.76,0)
  silkscreen extent -1.46,-0.7 1.46,0.7, body extent -0.8,-0.41 0.8,0.41, height 0.45
CONN-TH_XY2500R-F-3.81-2P [mm]
  round 2 hole 1.3 mask+0.051: 1(-1.905,0) 2(1.905,0)
  silkscreen extent -4.31,-7.7 4.31,1.4
HC-49US [mm]
  rect 1.5x1.5 hole 0.9 mask+0.051: 1(-2.44,0)
  round 1.5 hole 0.9 mask+0.051: 2(2.44,0)
  silkscreen extent -5.39,-2.25 5.39,2.25
HDR2.54-LI-2P [mm] "排针，2脚"
  rect 1.7x1.7 hole 0.9: 1(-1.27,0)
  round 1.7 hole 0.9: 2(1.27,0)
  silkscreen extent -2.54,-1.27 2.54,1.27, body extent -2.54,-1.27 2.54,1.27, height 8.5
HDR2.54-LI-2x2P [mm] "双排排针，2x2脚"
  rect 1.6x1.6 hole 0.9: 1(-1.27,-1.27)
  round 1.6 hole 0.9: 2(-1.27,1.27) 3(1.27,-1.27) 4(1.27,1.27)
  silkscreen extent -2.54,-2.54 2.54,2.54, body extent -2.54,-2.54 2.54,2.54, height 8.5
HDR2.54-LI-2x3P [mm] "双排排针，3x2脚"
  rect 1.6x1.6 hole 0.9: 1(-2.54,-1.27)
  round 1.6 hole 0.9: 2(-2.54,1.27) 3(0,-1.27) 4(0,1.27) 5(2.54,-1.27) 6(2.54,1.27)
  silkscreen extent -3.81,-2.54 3.81,2.54, body extent -3.81,-2.54 3.81,2.54, height 8.5
HDR2.54-LI-3P [mm] "排针，3脚"
  rect 1.7x1.7 hole 0.9: 1(-2.54,0)
  round 1.7 hole 0.9: 2(0,0) 3(2.54,0)
  silkscreen extent -3.81,-1.27 3.81,1.27, body extent -3.81,-1.27 3.81,1.27, height 8.5
HDR-TH_1P [mm]
  rect 1.8x1.8 hole 1.1 mask+0.051: 1(0,0)
  body extent -1.27,-1.27 1.27,1.27, height 8.5
HDR-TH_2x23P-P2.54-Bent [mm]
  round 1.6 hole 1.05 mask+0.051: 1(-27.94,1.27) 3(-25.4,1.27) 4(-25.4,-1.27) 5(-22.86,1.27) 6(-22.86,-1.27) 7(-20.32,1.27) 8(-20.32,-1.27) 9(-17.78,1.27) 10(-17.78,-1.27) 11(-15.24,1.27) 12(-15.24,-1.27) 13(-12.7,1.27) 14(-12.7,-1.27) 15(-10.16,1.27) 16(-10.16,-1.27) 17(-7.62,1.27) 18(-7.62,-1.27) 19(-5.08,1.27) 20(-5.08,-1.27) 21(-2.54,1.27) 22(-2.54,-1.27) 23(0,1.27) 24(0,-1.27) 25(2.54,1.27) 26(2.54,-1.27) 27(5.08,1.27) 28(5.08,-1.27) 29(7.62,1.27) 30(7.62,-1.27) 31(10.16,1.27) 32(10.16,-1.27) 33(12.7,1.27) 34(12.7,-1.27) 35(15.24,1.27) 36(15.24,-1.27) 37(17.78,1.27) 38(17.78,-1.27) 39(20.32,1.27) 40(20.32,-1.27) 41(22.86,1.27) 42(22.86,-1.27) 43(25.4,1.27) 44(25.4,-1.27) 45(27.94,1.27) 46(27.94,-1.27)
  rect 1.6x1.6 hole 1.05 mask+0.051: 2(-27.94,-1.27)
  silkscreen extent -29.4,-2.47 29.4,-2.47, body extent -29.21,-11.07 29.21,1.78, height 5.1
HDR-TH_16P-P2.54 [mm]
  rect 1.8x1.8 hole 1.1 mask+0.051: 1(-19.05,0)
  round 1.8 hole 1.1 mask+0.051: 2(-16.51,0) 3(-13.97,0) 4(-11.43,0) 5(-8.89,0) 6(-6.35,0) 7(-3.81,0) 8(-1.27,0) 9(1.27,0) 10(3.81,0) 11(6.35,0) 12(8.89,0) 13(11.43,0) 14(13.97,0) 15(16.51,0) 16(19.05,0)
  silkscreen extent -20.32,-1.27 20.32,1.27, body extent -20.32,-1.27 20.32,1.27, height 8.5
HDR-TH_32P-P2.54-V-M-R2-C16-S2.54 [mm]
  rect 2x2 hole 1.2 mask+0.051: 1(-19.05,-1.27)
  round 2 hole 1.2 mask+0.051: 2(-19.05,1.27) 3(-16.51,-1.27) 4(-16.51,1.27) 5(-13.97,-1.27) 6(-13.97,1.27) 7(-11.43,-1.27) 8(-11.43,1.27) 9(-8.89,-1.27) 10(-8.89,1.27) 11(-6.35,-1.27) 12(-6.35,1.27) 13(-3.81,-1.27) 14(-3.81,1.27) 15(-1.27,-1.27) 16(-1.27,1.27) 17(1.27,-1.27) 18(1.27,1.27) 19(3.81,-1.27) 20(3.81,1.27) 21(6.35,-1.27) 22(6.35,1.27) 23(8.89,-1.27) 24(8.89,1.27) 25(11.43,-1.27) 26(11.43,1.27) 27(13.97,-1.27) 28(13.97,1.27) 29(16.51,-1.27) 30(16.51,1.27) 31(19.05,-1.27) 32(19.05,1.27)
  silkscreen extent -20.32,-2.54 20.32,2.54
"L 0603" [mil] "小功率贴片电感"
  rect 35x35 smd: 1(-35,0) 2(35,0)
  silkscreen extent -65,-25 65,25, body extent -31,-16 31,16, height 31
"L 1206" [mil] "小功率贴片电感"
  rect 50x65 smd: 1(-67.5,0) 2(67.5,0)
  silkscreen extent -105,-45 105,45, body extent -63,-31 63,32, height 22
"LED 0603G" [mil] "绿色0603LED"
  rect 50x35 smd: A(-35,0.26)
  oct 50x35 smd: K(35,0.26)
  silkscreen extent -71,-28 81,28, body extent -31,-16 32,16, height 18
LQFP-64 [mm]
  oval 0.3x2 smd mask+0.051: 1(-3.75,-5.75) 2(-3.25,-5.75) 3(-2.75,-5.75) 4(-2.25,-5.75) 5(-1.75,-5.75) 6(-1.25,-5.75) 7(-0.75,-5.75) 8(-0.25,-5.75) 9(0.25,-5.75) 10(0.75,-5.75) 11(1.25,-5.75) 12(1.75,-5.75) 13(2.25,-5.75) 14(2.75,-5.75) 15(3.25,-5.75) 16(3.75,-5.75) 33(3.75,5.75) 34(3.25,5.75) 35(2.75,5.75) 36(2.25,5.75) 37(1.75,5.75) 38(1.25,5.75) 39(0.75,5.75) 40(0.25,5.75) 41(-0.25,5.75) 42(-0.75,5.75) 43(-1.25,5.75) 44(-1.75,5.75) 45(-2.25,5.75) 46(-2.75,5.75) 47(-3.25,5.75) 48(-3.75,5.75)
  oval 2x0.3 smd mask+0.051: 17(5.75,-3.75) 18(5.75,-3.25) 19(5.75,-2.75) 20(5.75,-2.25) 21(5.75,-1.75) 22(5.75,-1.25) 23(5.75,-0.75) 24(5.75,-0.25) 25(5.75,0.25) 26(5.75,0.75) 27(5.75,1.25) 28(5.75,1.75) 29(5.75,2.25) 30(5.75,2.75) 31(5.75,3.25) 32(5.75,3.75) 49(-5.75,3.75) 50(-5.75,3.25) 51(-5.75,2.75) 52(-5.75,2.25) 53(-5.75,1.75) 54(-5.75,1.25) 55(-5.75,0.75) 56(-5.75,0.25) 57(-5.75,-0.25) 58(-5.75,-0.75) 59(-5.75,-1.25) 60(-5.75,-1.75) 61(-5.75,-2.25) 62(-5.75,-2.75) 63(-5.75,-3.25) 64(-5.75,-3.75)
  silkscreen extent -5,-5.79 5,5, body extent -6,-6 6,6, height 1.45
M3x4_L [mil] "M3铜柱，长：4mm"
  round 200 hole 125: 1(0,0)
  silkscreen extent -157,-157 157,157, body extent -106,-93 106,93, height 159
"OSC 3225-4P" [mm] "3.2*2.5*0.7mm(长宽高)"
  rect 1.3x1.2 smd: 1(-1.05,-0.85) 2(1.05,-0.85) 3(1.05,0.85) 4(-1.05,0.85)
  silkscreen extent -2.03,-1.75 1.91,1.65, body extent -1.6,-1.25 1.6,1.25, height 0.7
RES-ADJ-TH_3362P [mil]
  round 60 hole 30 mask+2: 1(-100,-50) 2(0,50) 3(100,-50)
  silkscreen extent -140,-190 140,90
SMB_V-RJ45 [mm] "Connector; SMB Straight"
  round 2.5 hole 1.5: 1(0,0) 2(-2.5,-2.5) 2(-2.5,2.5) 2(2.5,-2.5) 2(2.5,2.5)
  silkscreen extent -3.15,-3.15 3.15,3.15
SOIC-8 [mil]
  oval 88x24 smd: 1(0,0) 2(0,-50) 3(0,-100) 4(0,-150) 5(320,-150) 6(320,-100) 7(320,-50) 8(320,0)
  silkscreen extent 60,-180 260,30, body extent -5,-181 325,31, height 91
SOT23-5 [mm]
  rect 0.5x1 smd: 1(0,0) 2(0.95,0) 3(1.9,0) 4(1.9,2.4) 5(0,2.4)
  silkscreen extent -0.55,0.4 2.45,2, body extent -0.5,-0.2 2.4,2.6, height 1.09
Tantalum_cap [mil]
  rect 69.19x51.02 smd mask+2: 1(-66.39,0) 2(66.39,0)
  silkscreen extent -81,-37 66,37, body extent -63,-31 63,32, height 63
TestPoint_Pad [mil]
  round 60 hole 30: 1(0,0)

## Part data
A1: library part SMB, "SMB Straight Connector"
C0-1 C0-2 C0-3 C0-4 C0-5 C0-6 C0-7 C0-8 C0-9 C0-10 C1-1 C2-1 C3-1 C4-1 C5-1 C6-1 C7-1 C8-1 C9-1 C10-1 C11-1 C12-1 C13-1 C14-1 C15-1 C16-1 C17 C17-1 C17-2 C18 C19 C19-1 C19-2 C20 C21 C21-1 C21-2 C22 C23 C24 C25 C26 C28 C30 C32 C33 C37 C38 C48 C48-1 C49 C49-1 C50 C51 C53-1 C53-2 C54-1 C54-2 C55-1 C55-2 C55-3 C55-4 C56-1 C56-2 C57-2 C58-2 C59-2 C61 C62-1 C62-2 C63-1 C63-2: library part C, "Chip  Ceramic Capacitor"
C57-1 C58-1 C59-1: library part Tantalum_cap, Equivalent Series Resistance(ESR)=7.5Ω@100kHz, JLCPCB Part Class="Extended Part", LCSC Part Name="1uF ±10% 35V", Manufacturer="Kyocera AVX", Manufacturer Part=TAJA105K035RNJ, Operating Temperature=-55¡æ~+125¡, Rated Voltage=35V, Tolerance=±10%
D1 D2: library part "0603 绿灯", "发光二极管", Package=0603, SuppliersPartNumber=C72043
H1 H2: "铜柱孔"
J9 JP2 JP3 JP10 JP11 JP25: "Header, 2-Pin, Dual row"
J11: library part Header1x16, Color=ºÚÉ, Current Rating (Max)=3A, JLCPCB Part Class="Extended Part", LCSC Part Name="2.54mm 1x16P Ö±²å ·", Manufacturer=kinghelm(½ðº½±, Operating Temperature Range=-40¡æ~+105¡, Voltage Rating (Max)=-
J12: library part Header_2.54mm_2x23P_Bent, Color=ºÚÉ, Current Rating (Max)=3A, JLCPCB Part Class="Extended Part", LCSC Part Name="2.54mm 2x23P 弯插 方针 高镀", Manufacturer="XKB Connectivity(中国星", Operating Temperature Range=-40¡æ~+105¡, Voltage Rating (Max)=250V, Welding Temperature (Max)=260℃
J16 TP1: Color=ºÚÉ, Current Rating (Max)=-, JLCPCB Part Class="Extended Part", LCSC Part Name="2.54mm 1x2P Ö±²å ·", Manufacturer=MOLEX, Manufacturer Part=22284020
JP1: library part Header2*16P, Color=ºÚÉ, Current Rating (Max)=-, JLCPCB Part Class="Extended Part", LCSC Part Name="2.54mm 2x16P Ö±²", Manufacturer=Ckmtw(²Ó¿ÆÃ, Operating Temperature Range=-40¡æ~+105¡
JP12 JP13 JP14 JP17 JP20 JP22 JP23 JP27 JP28 JP29 JP30 JP31 JP32 JP33 JP34 JP35 JP36 JP37 JP38 JP39 JP40 JP41 JP42: library part "Header 3", "3P接插件"
JP15: "Header, 3-Pin, Dual row"
JP18: Color=黑色, Current Rating (Max)=-, JLCPCB Part Class="Extended Part", LCSC Part Name="2.54mm 1x2P 直插 方针", Manufacturer=MOLEX, Manufacturer Part=22284020
JP26: library part "Header 3_1", "3P接插件"
L1 L4 L5: library part "L 1206", "小功率贴片电感"
L2 L3: library part CBW160808U000T, "磁珠", Current Rating=1A, DC Resistance=80mΩ, JLCPCB Part Class="Extended Part", LCSC Part Name="0¦¸@100MHz 0~15¦", Manufacturer=FH(风华, Tolerance=0~15Ω
R1-1 R2-1 R3-1 R4-1 R5-1 R6-1 R7-1 R8-1 R9-1 R10-1 R11-1 R12-1 R13-1 R14-1 R15-1 R16-1 R17 R17-1 R21 R23 R35 R36 R39 R48 R52 R60-2 R61 R62 R62-1 R62-2 R62-3 R63 R63-1 R63-2: library part R, "贴片电阻"
R60-1: library part 3362P-1-103, JLCPCB Part Class="Extended Part", LCSC Part Name="10kΩ ±10", Manufacturer=BOCHEN(博晨, Tolerance=±10%
TP2 TP3: library part TestPoint
U1: "ECG,EEG", Manufacturer_Part_Number=ADS131E08SPAG, Mfr_Name="Texas Instruments"
U2 U3 U6: library part LP5907MFX-3.3/NOPB, Dropout Voltage=250mV@(250mA), JLCPCB Part Class="Extended Part", LCSC Part Name="Vin{}5.5V Vout{}3.3V 250mA 90dB@(100Hz),60dB@(100kHz)", Manufacturer=TI(德州仪, Maximum Input Voltage=5.5V, Output Current=250mA, Output Voltage=3.3V, Power Supply Rejection Ratio (PRSS)=90dB@(100Hz),60dB@(100kHz)
U4-1: JLCPCB Part Class="Extended Part", Manufacturer=HGSEMI(华冠
U4-2: Dropout Voltage=500mV@(200mA), JLCPCB Part Class="Extended Part", LCSC Part Name="负 Vin{}10V Vout{}2.5V 200mA 65dB", Manufacturer=TI(德州仪器), Maximum Input Voltage=10V, Output Current=200mA, Output Voltage=2.5V, Power Supply Rejection Ratio (PSRR)=65dB
U5: Dropout Voltage=250mV@(250mA), JLCPCB Part Class="Extended Part", LCSC Part Name="Vin{}5.5V Vout{}3.3V 250mA 90dB@(100Hz),60dB@(100kHz)", Manufacturer=TI(德州仪, Maximum Input Voltage=5.5V, Output Current=250mA, Output Voltage=3.3V, Power Supply Rejection Ratio (PRSS)=90dB@(100Hz),60dB@(100kHz)
U7: JLCPCB Part Class="Extended Part", Manufacturer=TI(德州仪, Operating Temperature=-
U8 U9: JLCPCB Part Class="Extended Part", Manufacturer=TI(德州仪
X1: Frequency Stability=±20ppm, JLCPCB Part Class="Extended Part", LCSC Part Name="2.048MHz ±20ppm 1.62V~3.63V CMOS", Manufacturer=SCTF(星通时, Operating Temperature=-40¡æ~+85¡, Supply Current (Max)=10mA, Supply Voltage=1.62V~3.63V
X2: library part "Passive Oscillator", Frequency Stability=±30ppm, Frequency Tolerance=±20ppm, JLCPCB Part Class="Extended Part", LCSC Part Name="HC-49US 4.096MHz ±20ppm 20pF", Load Capacitance=20pF, Manufacturer=YXC(扬兴晶, Manufacturer Part=X49SD4096MSD2SC-1, Operating Temperature=-20¡æ~+70¡

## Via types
v1: diameter 20, hole 12, Top Layer to Bottom Layer, tented both sides, 86 vias
v2: diameter 20, hole 12, Top Layer to Bottom Layer, 15 vias

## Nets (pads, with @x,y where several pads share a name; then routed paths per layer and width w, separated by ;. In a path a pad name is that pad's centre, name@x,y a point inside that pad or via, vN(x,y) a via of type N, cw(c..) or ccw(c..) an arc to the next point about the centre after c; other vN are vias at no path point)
5V_Select: JP26.2 L1.1 | length 124.1
  Top Layer w20: L1.1@3465.5,3315 3554.3,3315 3570.3,3299 JP26.2@3583,3299
+1.8V: C51.2 JP13.3 U6.5 | length 232.2
  Top Layer w20: U6.5@2267,3604.51 2267,3528.87 2261.92,3523.79 C51.2@2261.92,3523 2261.92,3426.78 2290,3398.7 JP13.3@2290,3386
+2.5V: C22.2 JP15.2 U3.5 | length 195.7
  Top Layer w20: JP15.2@2374,1033 2385.63,1033 2407.55,1011.08 C22.2@2487,1011.08 ; C22.2@2495.87,1003 U3.5@2569.51,1003
+3.0V: C20.2 JP15.4 U2.5 | length 230.1
  Top Layer w20: JP15.4@2374,933 2382.23,924.77 2401.44,924.77 2488.21,838 C20.2@2489,838 2489.79,838 2495.19,832.6 U2.5@2562.51,832.6
+3.3V: C49.2 JP11.3 JP13.1 U5.5 | length 779
  Top Layer w20: U5.5@2566,3609.51 2566,3599.98 2559.92,3593.91 C49.2@2559.92,3525 2559.92,3455.92 JP13.1@2490,3386 2799,3386 JP11.3@2951,3234
+5V: C0-1.2 C0-2.2 C19.2 C21.2 C48.2 C50.2 C58-1.1 JP15.6 L1.2 U2.1 U2.3 U3.1 U3.3 U4-1.8 U5.1 U5.3 U6.1 U6.3 | length 1818
  Top Layer w20: C48.2@2192.2,3775.41 U6.3@2192.2,3699 2192.35,3698.84 2192.35,3678.43 2212.79,3658 2252,3658 2266.84,3672.84 2266.84,3698.84 U6.1@2267,3699 ; C48.2@2200,3784 2200,3784.79 2264.21,3849 v1(2292,3849) ; JP15.6@2374,833 2470.79,736.21 2470.79,722.51 2486.31,707 C58-1.1@2492.51,707 ; v1(2459,3860) 2490,3829 C50.2@2490,3786 2490,3740.25 2491.04,3739.21 2491.04,3704.16 U5.3@2491.2,3704 2491.35,3703.84 2491.35,3676.65 2518,3650 2546,3650 2565.84,3669.84 2565.84,3703.84 U5.1@2566,3704 ; C58-1.1@2516,691.49 2500.49,707 C58-1.1@2495.39,707 C58-1.1@2492.51,707 ; v1(2567.3,581.3) 2538.7,581.3 2510.31,609.69 2478.31,609.69 U4-1.8@2477,611 2477,691.49 C58-1.1@2492.51,707 ; U3.1@2664,1003 2673.53,1003 2707.35,969.18 2757.82,969.18 2773.69,953.31 2773.69,936.74 2743.79,906.84 C19.2@2743,906.84 C19.2@2742.6,907.24 ; U3.3@2664,1077.8 2664.16,1077.65 2739.28,1077.65 C21.2@2740,1076.92 2803.92,1076.92 v1(2805,1078) ; v1(2719,791) 2708.13,791 2666.53,832.6 U2.1@2657,832.6 2656.84,832.76 2624.24,832.76 2607,850 2607,891 2623.24,907.24 2656.84,907.24 U2.3@2657,907.4 2657.16,907.24 C19.2@2742.6,907.24 ; C19.2@2737.25,911.8 2738.04,911.8 C19.2@2742.6,907.24 ; 3350.97,3236.03 3351.76,3236.03 ; C0-1.2@3385,3202.79 C0-1.2@3385,3202 C0-1.2@3385,3202 3385.04,3116.04 C0-2.2@3385.08,3116 C0-2.2@3385.08,3115.21
  other v1: 3289,3095 3289,3158 3288,3217
+5V_Ctrl: C0-5.2 C0-6.2 J12.45 J14.1 JP26.1 | length 707.2
  Top Layer w20: JP26.1@3583,3199 3587,3195 J14.1@3721,3195 ; C0-5.2@3768.12,3405.96 C0-5.2@3763.16,3401 3764.12,3400.04 3764.12,3322.96 C0-6.2@3765.08,3322 3765.08,3321.21 3721,3277.13 J14.1@3721,3195 ; J12.45@3794.88,2901.88 J12.45@3789,2896 3721,2964 J14.1@3721,3195
+5V_EXT: C0-3.2 C0-4.2 JP26.3 Power.1 | length 558.6
  Top Layer w20: C0-3.2@3264.92,3500 3266.42,3498.5 3266.42,3411.71 3279.13,3399 JP26.3@3583,3399 ; C0-3.2@3264.92,3500.79 3264.92,3575.92 3310,3621 Power.1@3310,3630
-2.5V: C0-9.2 C59-2.2 L5.1 U4-2.5 | length 315.3
  Top Layer w20: U4-2.5@2916.49,615 2916.49,687.65 2909.92,694.21 C59-2.2@2909.92,695 2909.46,695.46 2909.46,803.25 2944.71,838.5 L5.1@3019,838.5
-5V: C57-2.2 C59-1.2 U4-1.5 U4-2.2 U4-2.3 | length 432.7
  Top Layer w20: U4-1.5@2477,461 2607.47,461 2653,506.53 C59-1.2@2653,515.61 2708.51,515.61 2741.25,548.35 2741.25,549.12 2746.21,554.08 C57-2.2@2747,554.08 2747.79,554.08 2761.67,540.2 U4-2.3@2822,540.2 2822.16,540.35 2822,540.35 U4-2.2@2822,577.6
AGND: A1.2 C0-1.1 C0-2.1 C0-7.1 C0-8.1 C0-9.1 C0-10.1 C1-1.1 C2-1.2 C3-1.1 C4-1.2 C5-1.1 C6-1.2 C7-1.1 C8-1.2 C9-1.1 C10-1.2 C11-1.1 C12-1.2 C13-1.1 C14-1.2 C15-1.1 C16-1.2 C17-1.1 C17-2.1 C17.1 C18.2 C19.1 C20.1 C21.1 C22.1 C32.1 C33.1 C37.1 C38.2 C48-1.1 C48.1 C49-1.1 C49.1 C50.1 C51.1 C54-1.1 C54-2.1 C55-1.1 C55-2.1 C57-2.1 C58-1.2 C58-2.1 C59-1.1 C59-2.1 C62-1.1 C62-2.2 C63-1.1 C63-2.2 D1.K H1.1 H2.1 JP10.4 JP11.1 JP12.3 JP14.1 L2.2 L3.1 U1.31 U1.33 U1.49 U1.51 U1.64 U2.2 U2.4 U3.2 U3.4 U4-1.3 U4-1.6 U4-2.1 U5.2 U5.4 U6.2 U6.4 X1.2 | length 7354.4
  Top Layer w10: v1(1747,2311) 1748.91,2312.91 1773.82,2312.91 1819.31,2267.42 1833.52,2267.42 1834.36,2266.58 U1.64@1834.36,2252.37 ; U1.51@2090,2252.1 U1.51@2090.27,2252.37 2090.62,2252.72 2090.62,2293.24 2102.12,2304.74 2117.78,2304.74 2129.29,2293.23 ; U1.31@2109.95,1799.63 2109.95,1860.95 2127.36,1878.36 U1.33@2208.37,1878.36 2293.85,1878.36 2312.21,1860 C33.1@2313,1860 ; v1(2207,2253) 2130.27,2253 U1.49@2129.64,2252.37 2129.64,2301.64 2158,2330 2222,2330 2235.92,2343.92 C55-2.1@2235.92,2376
  Top Layer w20: v2(799,2304) 801.97,2306.97 C10-1.2@881.08,2306.97 C9-1.1@881.08,2389.58 ; v2(801,1732) 804.32,1728.68 C13-1.1@881.08,1728.68 C14-1.2@881.08,1646.06 ; v2(801,2058) 802.13,2059.13 C11-1.1@881.08,2059.13 C12-1.2@881.08,1976.52 ; v2(804,2635) 806.42,2637.42 C8-1.2@881.08,2637.42 C7-1.1@881.08,2720.03 ; v2(804,2968) 804.13,2967.87 C6-1.2@881.08,2967.87 C5-1.1@881.08,3050.48 ; v2(805,3300) 806.68,3298.32 C4-1.2@881.08,3298.32 C3-1.1@881.08,3380.94 ; v2(808,3624) 812.77,3628.77 C2-1.2@881.08,3628.77 C1-1.1@881.08,3711.39 ; v2(819,1453) 820,1452 828.09,1452 881.08,1399.01 C15-1.1@881.08,1398.23 C16-1.2@881.08,1315.61 ; C17.1@883.21,648.92 C17.1@884,648.92 884.5,648.42 966.5,648.42 C62-1.1@967,647.92 967.79,647.92 983.79,631.92 C17-1.1@1240,631.92 1240,726 v1(1249,735) ; v1(1085,677) 1088.21,680.21 1088.21,742.12 1089,742.91 C17-2.1@1089,747.08 ; C62-2.2@1125,89.08 1129.96,84.12 1149.84,84.12 1150.96,83 1428.13,83 1456.21,111.08 C18.2@1457,111.08 1556.08,111.08 v1(1557,112) ; C0-7.1@2149.92,960 2151.46,958.46 2151.46,822.38 C0-8.1@2153,820.84 ; U4-1.3@2157,511 U4-1.6@2477,511 2554,511 v1(2556,509) ; JP12.3@2187,3010 2189,3012 v1(2318,3012) ; C51.1@2192.2,3533.67 U6.4@2192.2,3604.51 ; JP12.3@2195,2990 JP12.3@2200,2985 ; C51.1@2202.08,3523 2202.08,3522.21 2168.83,3488.97 2168.05,3488.97 2147,3467.92 C54-2.1@2147,3429.92 2201.92,3429.92 v1(2203,3431) ; U6.2@2229.6,3699 2229.6,3752.97 2259.84,3783.21 C48.1@2259.84,3784 2262.34,3781.5 2377.25,3781.5 D1.K@2379.74,3779 2379.74,3855.26 v1(2377,3858) ; C55-2.1@2235.92,2376 C55-1.1@2235.92,2454 ; 2276,709 2278,707 C58-1.2@2362.61,707 ; C33.1@2315,1858.79 2315.79,1858 v1(2400,1858) ; C48-1.1@2365,2219.08 C49-1.1@2448,2219.08 v1(2554.08,2219.08) ; C63-1.1@2375.92,2779 C54-1.1@2375.92,2700 C32.1@2375.92,2622 C63-2.2@2375.92,2547 v1(2461,2547) ; C22.1@2487,1070.92 2487.79,1070.92 2494.67,1077.8 U3.4@2569.51,1077.8 2579.04,1077.8 2579.2,1077.65 2579.2,1075.52 2614.31,1040.4 U3.2@2664,1040.4 2715.89,1040.4 2739.21,1017.08 C21.1@2740,1017.08 2870.92,1017.08 JP14.1@2884,1004 ; C20.1@2489,897.84 2489.79,897.84 2499.35,907.4 U2.4@2562.51,907.4 ; C49.1@2491.2,3534.67 U5.4@2491.2,3609.51 ; v1(2499,3472) 2500.08,3473.08 C49.1@2500.08,3525 ; v1(2509.25,3048.25) 2631.04,3048.25 2631.04,3049.04 C37.1@2626.08,3054 2625.31,3054.77 2625.31,3139.89 X1.2@2624.54,3140.66 2620.37,3144.83 2544.17,3144.83 C38.2@2540,3149 ; v1(2528,1334) JP10.4@2528,1509 ; U5.2@2528.6,3704 2528.6,3763.97 2549.84,3785.21 C50.1@2549.84,3786 2549.84,3863.16 v1(2549,3864) ; v1(2562,645) 2565,648 2652.61,648 C59-1.1@2653,648.39 ; C59-1.1@2653,639.31 2678.38,613.92 C57-2.1@2747,613.92 2811.39,613.92 2812.47,615 U4-2.1@2822,615 ; U2.2@2657,870 2657.16,869.84 2677.57,869.84 2700.41,847 C19.1@2743,847 2743.79,847 2788.79,802 C0-9.1@2849.16,802 2849.62,801.54 2849.62,695.46 C59-2.1@2850.08,695 2851,694.08 2851,649 ; 2956,1076 2956,1122 2957,1123 ; C58-2.1@2995,605.92 2995.79,605.92 3030.94,641.08 C0-10.1@3118,641.08 ; v1(3443,3007) 3444.92,3008.92 C0-2.1@3444.92,3116 C0-2.1@3444.92,3116 3444.88,3201.96 C0-1.1@3444.84,3202 C0-1.1@3444.84,3201.21
  other v1: 2088,406 2085,539 3276.04,698.67 3277.04,766.67 3076,772 3180.58,793 3276.04,840.67 3178.58,883 2860,922 2899,922 2937,922 3070,928 3173.58,964 2937,1101 2860,1102 2897,1102 3071.42,3258 3129,3258 3196.96,3258
AIN1: JP1.2 R1-1.1 | length 785.7
  Top Layer w10: JP1.2@572,3152 572,3484.13 881.08,3793.21 R1-1.1@881.08,3794 ; R1-1.1@874.33,3783.25 875.12,3783.25 885.08,3793.21 R1-1.1@885.08,3794
AIN2: JP1.4 R2-1.1 | length 622.2
  Top Layer w10: JP1.4@572,3052 728.14,3208.14 728.14,3392.43 881.08,3545.37 R2-1.1@881.08,3546.16
AIN3: JP1.6 R3-1.1 | length 640.4
  Top Layer w10: JP1.6@572,2952 746.14,3126.14 746.14,3327.82 881.08,3462.76 R3-1.1@881.08,3463.55 ; R3-1.1@892,3456.21 R3-1.1@892,3457
AIN4: JP1.8 R4-1.1 | length 492.2
  Top Layer w10: JP1.8@572,2852 765,3045 765,3099.63 870.33,3204.96 871.12,3204.96 881.08,3214.92 R4-1.1@881.08,3215.71
AIN5: JP1.10 R5-1.1 | length 509.1
  Top Layer w10: JP1.10@572,2752 728.14,2908.14 728.14,2979.37 881.08,3132.31 R5-1.1@881.08,3133.1
AIN6: JP1.12 R6-1.1 | length 405.7
  Top Layer w10: JP1.12@572,2652 805.26,2885.26 R6-1.1@881.08,2885.26
AIN7: JP1.14 R7-1.1 | length 413.4
  Top Layer w10: JP1.14@572,2552 631.22,2552 881.08,2801.86 R7-1.1@881.08,2802.65
AIN8: JP1.16 R8-1.1 | length 352.1
  Top Layer w10: JP1.16@572,2452 779.06,2452 881.08,2554.02 R8-1.1@881.08,2554.81
AIN9: JP1.18 R9-1.1 | length 359.3
  Top Layer w10: JP1.18@572,2352 761.67,2352 881.08,2471.41 R9-1.1@881.08,2472.19
AIN10: JP1.20 R10-1.1 | length 321
  Top Layer w10: JP1.20@572,2252 854.22,2252 881.08,2225.14 R10-1.1@881.08,2224.35
AIN11: JP1.22 R11-1.1 | length 313.5
  Top Layer w10: JP1.22@572,2152 871.12,2152 881.08,2142.04 R11-1.1@881.08,2141.74
AIN12: JP1.24 R12-1.1 | length 375
  Top Layer w10: JP1.24@572,2052 723.77,2052 881.08,1894.69 R12-1.1@881.08,1893.9
AIN13: JP1.26 R13-1.1 | length 367.8
  Top Layer w10: JP1.26@572,1952 741.16,1952 881.08,1812.08 R13-1.1@881.08,1811.29
AIN14: JP1.28 R14-1.1 | length 429.1
  Top Layer w10: JP1.28@572,1852 849.8,1574.2 871.12,1574.2 881.08,1564.24 R14-1.1@881.08,1563.45
AIN15: JP1.30 R15-1.1 | length 421.4
  Top Layer w10: JP1.30@572,1752 843.16,1480.84 R15-1.1@881.08,1480.84
AIN16: JP1.32 R16-1.1 | length 562.9
  Top Layer w10: JP1.32@572,1652 572,1633.4 588.95,1616.45 588.95,1612.05 822,1379 822,1265 854,1233 R16-1.1@881.08,1233
AVDD: C0-7.2 C17-1.2 C19-1.2 C19-2.2 C21-1.2 C21-2.2 C23.2 C53-1.2 C53-2.2 C54-1.2 C54-2.2 C56-1.2 C56-2.2 C62-1.2 C63-1.2 L4.1 R21.2 R60-1.1 R62-1.2 TP2.1 U1.19 U1.21 U1.22 U1.54 U1.56 U1.59 U7.5 U8.7 U9.7 | length 3213.5
  Top Layer w10: v1(1850,1917) 1873.73,1893.27 U1.19@1873.73,1799.63 ; v1(1884,2147) 1932.79,2195.79 U1.59@1932.79,2252.37 ; U1.22@1932.79,1799.63 1932.79,1751.77 ; v1(1935,1917) 1932.29,1917 1920.47,1905.17 1920.17,1905.17 1913.1,1898.1 U1.21@1913.1,1799.63 1913.1,1757.63 1918.96,1751.77 1932.79,1751.77 ; C19-1.2@1964.92,1671 1964.92,1671.79 1932.79,1703.92 1932.79,1751.77 ; v1(1978,2334) 1991.84,2320.16 1991.84,2195.62 1998.3,2189.16 2025.35,2189.16 2031.21,2195.02 U1.54@2031.21,2252.37
  Top Layer w20: v1(907,368) 909,370 U9.7@909,464 909,530.87 966.21,588.08 C62-1.2@967,588.08 972.67,588.08 C62-1.2@972.75,588 ; v1(1173,572) 1173.08,572.08 C17-1.2@1240,572.08 1240,521.08 1263,498.08 U8.7@1263,465 ; R62-1.2@1455,472.92 1455,579 v1(1459,583) ; v1(1759,772) 1865,878 L4.1@2031,878 2038.5,878 2085.12,924.62 2085.12,955.04 C0-7.2@2090.08,960 2089.58,960.5 C23.2@2089.58,1037 ; v1(1779,3001) 1780.2,2999.8 U7.5@1780.2,2890 ; v1(1905,3371) 1905.92,3370.08 C53-2.2@2069,3370.08 C54-2.2@2147,3370.08 ; C21-1.2@1916,1467.92 C21-2.2@1992.21,1467.92 ; C19-1.2@1964.92,1671 C19-2.2@1964.92,1588 1964.92,1495.21 C21-2.2@1992.21,1467.92 ; R21.2@1970,993.08 2003.11,993.11 2047,1037 C23.2@2089.08,1037 2089.08,1101.1 2062,1128.18 TP2.1@2062,1139 ; C21-2.2@1993,1467.92 C21-2.2@1992.21,1467.92 ; C53-1.2@2177,2674 C53-1.2@2177,2674 2177.04,2747.96 C56-2.2@2177.08,2748 2177.58,2748.5 2177.58,2824.5 C56-1.2@2178.08,2825 v1(2178.08,2904.92) ; C54-1.2@2316.08,2700 C63-1.2@2316.08,2779 v1(2316.08,2902.92)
